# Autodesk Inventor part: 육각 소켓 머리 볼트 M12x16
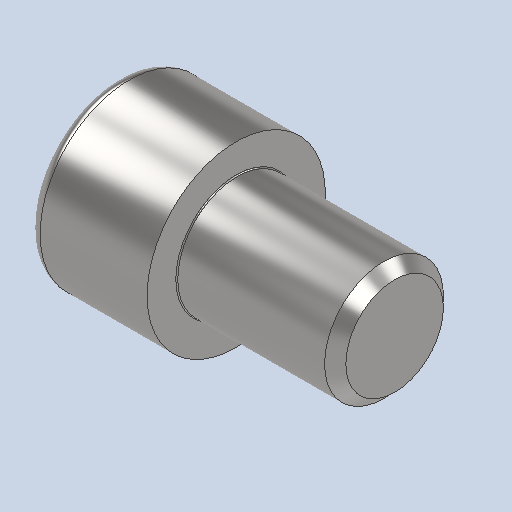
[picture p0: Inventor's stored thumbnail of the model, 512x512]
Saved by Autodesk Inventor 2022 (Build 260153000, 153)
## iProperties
Created: 2024-07
Part Number: 육각 소켓 머리 볼트 M12x16
Material: 강철, 연강
Description: 6각머리 태핑 나사
Document SubType Name: Modeling
Designer: PC-01
Density: 7.85 g/cm^3
Appearance: 기본값
Author: jhkim
Sending System: Autodesk Inventor 2025
Preprocessor: ST-DEVELOPER v20
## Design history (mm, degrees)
feature "Solid1"
node "솔리드1"
